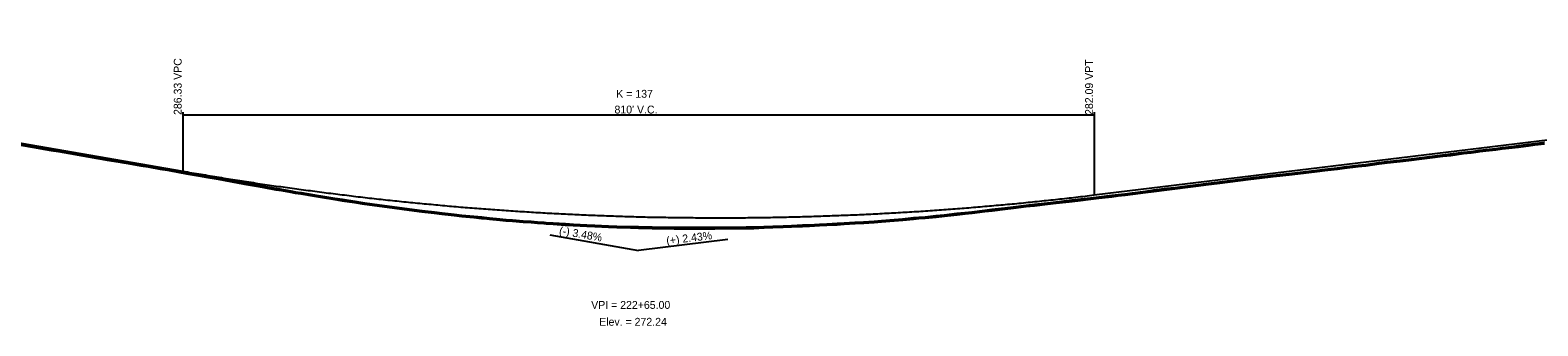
# Model space of a CAD drawing. Extents: x 1876258 to 1926563, y 729739 to 834437.
# Drawn here: x 1900087 to 1901427, y 831298 to 831561 of the extents above; entities that cross this region are included whole.
import ezdxf

# ---------------------------------------------------------------- set-up
doc = ezdxf.new("R2010")
doc.units = 0
for name, color, linetype in [('RD_EX_BldgApp', 7, 'Continuous'), ('RD_EX_H2O_BlueLn', 7, 'Continuous'), ('RD_EX_RailRoad', 7, 'Continuous'), ('RD_HC_Data', 7, 'Continuous'), ('RD_HC_Data_Tic', 7, 'Continuous'), ('RD_HC_TX_Sta50', 7, 'Continuous'), ('RD_PD_ALT5_CL', 7, 'Continuous')]:
    doc.layers.add(name, color=color, linetype=linetype)

msp = doc.modelspace()

# ---------------------------------------------------------------- linework, layer by layer
at = {"layer": 'RD_EX_BldgApp'}
for points in [[(1900079.3, 831459), (1900089.5, 831457.2), (1900095.9, 831456.1), (1900106.1, 831454.4), (1900112.5, 831453.3), (1900122.7, 831451.5), (1900129.1, 831450.4), (1900139.3, 831448.7), (1900145.7, 831447.6), (1900151.1, 831446.6), (1900155.9, 831445.8), (1900165.6, 831444.1), (1900168.8, 831443.6), (1900174.7, 831442.6), (1900185.8, 831440.8), (1900192.2, 831439.7), (1900203, 831437.8), (1900209.4, 831436.7), (1900220.1, 831434.8), (1900226.4, 831433.7), (1900237.2, 831431.8), (1900243.7, 831430.6), (1900254.4, 831428.7), (1900260.8, 831427.6), (1900271.6, 831425.7), (1900277.9, 831424.5), (1900288.7, 831422.5), (1900295.1, 831421.4), (1900305.9, 831419.4), (1900310.7, 831418.7), (1900318.8, 831417.2), (1900323, 831416.5), (1900328.1, 831415.7), (1900340.1, 831413.7), (1900347.3, 831412.5), (1900358.1, 831410.8), (1900364.8, 831409.7), (1900375.8, 831408), (1900382.5, 831407), (1900393.4, 831405.4), (1900400.2, 831404.4), (1900411.2, 831402.9), (1900417.9, 831402), (1900428.8, 831400.7), (1900435.7, 831399.8), (1900446.6, 831398.6), (1900453.4, 831397.7), (1900464.2, 831396.4), (1900471.1, 831395.6)], [(1901312.7, 831445.5), (1901324.4, 831446.9), (1901331.4, 831447.8), (1901342.9, 831449.2), (1901350, 831450), (1901361.4, 831451.5), (1901368.2, 831452.3), (1901374.3, 831453.1), (1901375.8, 831453.3), (1901381.3, 831454), (1901390.1, 831455), (1901395.8, 831455.7), (1901404.6, 831456.8), (1901410.3, 831457.4), (1901419, 831458.5), (1901424.8, 831459.3), (1901433.4, 831460.3)], [(1900471.1, 831395.6), (1900481.8, 831394.6), (1900488.7, 831393.9), (1900493.2, 831393.5), (1900495.7, 831393.2), (1900504.8, 831392.4), (1900510.3, 831391.8), (1900516, 831391.4), (1900525.5, 831390.6), (1900532.6, 831390.2), (1900538.4, 831389.7), (1900544.1, 831389.3), (1900546.1, 831389.1), (1900552.4, 831388.7), (1900563, 831388), (1900570.2, 831387.6), (1900582.1, 831387), (1900589.3, 831386.7), (1900601.4, 831386.1), (1900608.9, 831385.8), (1900621, 831385.5), (1900628.2, 831385.3), (1900640.4, 831385.1), (1900648, 831385), (1900659.8, 831384.8), (1900671.7, 831384.7), (1900679.1, 831384.7), (1900688.4, 831384.8), (1900695.9, 831384.8), (1900705.4, 831384.9), (1900711.8, 831385), (1900714.6, 831384.9), (1900723.9, 831385), (1900730.7, 831385.1), (1900739.7, 831385.4), (1900747.5, 831385.7), (1900756.7, 831386.1), (1900764.2, 831386.4), (1900774, 831386.8), (1900780, 831387.1), (1900789.1, 831387.5), (1900795.5, 831387.8), (1900804.7, 831388.3), (1900811, 831388.7), (1900820.6, 831389.3), (1900828.3, 831389.8), (1900837.7, 831390.4), (1900844.2, 831390.9), (1900855.4, 831391.7), (1900863, 831392.4), (1900872.6, 831393.3), (1900877.3, 831393.7), (1900883, 831394.1), (1900892.6, 831395.1), (1900900, 831395.9), (1900911.3, 831397.2), (1900918.5, 831398), (1900924.6, 831398.7), (1900936, 831400), (1900942.4, 831400.7), (1900953.9, 831402.1), (1900961.3, 831403), (1900972.7, 831404.4), (1900980.1, 831405.2), (1900991.7, 831406.6), (1900999.3, 831407.5), (1901011, 831408.8), (1901018.5, 831409.7), (1901030.2, 831411), (1901037.4, 831411.8), (1901048.9, 831413.2), (1901054.5, 831413.9), (1901060.6, 831414.7), (1901067.5, 831415.6), (1901078.8, 831417), (1901086.1, 831417.9), (1901097.8, 831419.4), (1901104.9, 831420.3), (1901116.3, 831421.7), (1901123.4, 831422.6), (1901134.8, 831424.1), (1901142.3, 831425), (1901153.9, 831426.5), (1901160.9, 831427.4), (1901172.4, 831428.7), (1901180, 831429.6), (1901192.1, 831431.1), (1901198.1, 831431.8), (1901209, 831433), (1901214, 831433.5), (1901221.4, 831434.4), (1901231.4, 831435.6), (1901238.2, 831436.5), (1901249.4, 831437.8), (1901255.5, 831438.6), (1901267.8, 831440), (1901274.5, 831440.8), (1901286.3, 831442.3), (1901293.4, 831443.2), (1901305.1, 831444.6), (1901312.7, 831445.5)]]:
    msp.add_lwpolyline(points, dxfattribs=at)
at = {"layer": 'RD_EX_H2O_BlueLn'}
for p, q in [((1900223.1, 831488.4), (1900223.1, 831435.9)), ((1900223.1, 831485.9), (1901033.1, 831485.9)), ((1901033.1, 831488.4), (1901033.1, 831414.8))]:
    msp.add_line(p, q, dxfattribs=at)
at = {"layer": 'RD_HC_Data_Tic'}
msp.add_lwpolyline([(1900079.5, 831460.2), (1900089.7, 831458.4), (1900096.1, 831457.3), (1900106.3, 831455.6), (1900112.7, 831454.5), (1900122.9, 831452.7), (1900129.3, 831451.6), (1900139.5, 831449.9), (1900145.9, 831448.8), (1900151.3, 831447.8), (1900156.1, 831447), (1900165.8, 831445.3), (1900169, 831444.8), (1900174.9, 831443.8), (1900186, 831442), (1900192.4, 831440.9), (1900203.2, 831439), (1900209.6, 831438), (1900220.3, 831436.1), (1900226.7, 831434.9), (1900237.4, 831433), (1900243.9, 831431.8), (1900254.6, 831429.9), (1900261, 831428.8), (1900271.8, 831426.9), (1900278.2, 831425.7), (1900288.9, 831423.8), (1900295.3, 831422.6), (1900306.1, 831420.7), (1900310.9, 831419.9), (1900319, 831418.5), (1900323.2, 831417.7), (1900328.3, 831416.9), (1900340.3, 831414.9), (1900347.5, 831413.7), (1900358.3, 831412), (1900365, 831411), (1900376, 831409.3), (1900382.7, 831408.2), (1900393.6, 831406.6), (1900400.4, 831405.6), (1900411.4, 831404.1), (1900418.1, 831403.2), (1900428.9, 831401.9), (1900435.8, 831401.1), (1900446.7, 831399.8), (1900453.5, 831399), (1900464.4, 831397.7), (1900471.2, 831396.9), (1900481.9, 831395.8), (1900488.9, 831395.2), (1900493.3, 831394.7), (1900495.8, 831394.5), (1900504.9, 831393.6), (1900510.4, 831393.1), (1900516.1, 831392.6), (1900525.6, 831391.8), (1900532.7, 831391.4), (1900538.5, 831391), (1900544.2, 831390.5), (1900546.2, 831390.4), (1900552.4, 831389.9), (1900563.1, 831389.3), (1900570.3, 831388.9), (1900582.2, 831388.2), (1900589.3, 831387.9), (1900601.5, 831387.3), (1900609, 831387.1), (1900621, 831386.8), (1900628.2, 831386.6), (1900640.4, 831386.3), (1900648, 831386.2), (1900659.8, 831386), (1900671.7, 831386), (1900679.1, 831386), (1900688.4, 831386), (1900695.9, 831386), (1900705.4, 831386.2), (1900711.8, 831386.2), (1900714.6, 831386.2), (1900723.9, 831386.3), (1900730.7, 831386.4), (1900739.6, 831386.7), (1900747.4, 831387), (1900756.7, 831387.3), (1900764.1, 831387.6), (1900774, 831388.1), (1900780, 831388.3), (1900789, 831388.8), (1900795.4, 831389.1), (1900804.6, 831389.6), (1900811, 831389.9), (1900820.5, 831390.5), (1900828.2, 831391), (1900837.6, 831391.6), (1900844.1, 831392.2), (1900855.3, 831393), (1900862.9, 831393.6), (1900872.4, 831394.6), (1900877.2, 831395), (1900882.9, 831395.4), (1900892.5, 831396.4), (1900899.9, 831397.2), (1900911.2, 831398.5), (1900918.3, 831399.2), (1900924.5, 831399.9), (1900935.9, 831401.3), (1900942.2, 831402), (1900953.8, 831403.4), (1900961.1, 831404.2), (1900972.6, 831405.6), (1900980, 831406.5), (1900991.5, 831407.8), (1900999.2, 831408.8), (1901010.8, 831410.1), (1901018.4, 831410.9), (1901030, 831412.2), (1901037.3, 831413.1), (1901048.7, 831414.5), (1901054.4, 831415.2), (1901060.4, 831415.9), (1901067.3, 831416.8), (1901078.6, 831418.2), (1901086, 831419.2), (1901097.7, 831420.7), (1901104.7, 831421.5), (1901116.1, 831422.9), (1901123.2, 831423.8), (1901134.6, 831425.3), (1901142.1, 831426.2), (1901153.8, 831427.7), (1901160.8, 831428.6), (1901172.2, 831430), (1901179.8, 831430.8), (1901192, 831432.3), (1901197.9, 831433), (1901208.8, 831434.2), (1901213.8, 831434.8), (1901221.2, 831435.6), (1901231.2, 831436.9), (1901238, 831437.7), (1901249.2, 831439), (1901255.3, 831439.8), (1901267.7, 831441.3), (1901274.3, 831442), (1901286.1, 831443.5), (1901293.2, 831444.4), (1901304.9, 831445.8), (1901312.6, 831446.7), (1901324.2, 831448.1), (1901331.3, 831449), (1901342.8, 831450.4), (1901349.9, 831451.3), (1901361.3, 831452.7), (1901368.1, 831453.5), (1901374.1, 831454.3), (1901375.6, 831454.5), (1901381.1, 831455.2), (1901390, 831456.2), (1901395.7, 831457), (1901404.4, 831458), (1901410.1, 831458.7), (1901418.8, 831459.8), (1901424.6, 831460.5), (1901433.3, 831461.6)], dxfattribs=at)
at = {"layer": 'RD_HC_TX_Sta50'}
for p in [(1900549.3, 831379.2), (1900707.5, 831375.2)]:
    msp.add_line(p, (1900628.1, 831365.5), dxfattribs=at)
at = {"layer": 'RD_PD_ALT5_CL'}
for p, q in [((1901033.1, 831414.8), (1902238.1, 831561.3)), ((1900053.1, 831465.5), (1900223.1, 831435.9))]:
    msp.add_line(p, q, dxfattribs=at)
msp.add_spline([(1900223.1, 831435.9), (1900239.3, 831433.2), (1900255.5, 831430.5), (1900271.7, 831427.9), (1900287.9, 831425.4), (1900304.1, 831423), (1900320.3, 831420.8), (1900336.5, 831418.6), (1900352.7, 831416.5), (1900368.9, 831414.5), (1900385.1, 831412.5), (1900401.3, 831410.7), (1900417.5, 831409), (1900433.7, 831407.4), (1900449.9, 831405.9), (1900466.1, 831404.4), (1900482.3, 831403.1), (1900498.5, 831401.9), (1900514.7, 831400.7), (1900530.9, 831399.7), (1900547.1, 831398.7), (1900563.3, 831397.9), (1900579.5, 831397.1), (1900595.7, 831396.5), (1900611.9, 831395.9), (1900628.1, 831395.4), (1900644.3, 831395), (1900660.5, 831394.8), (1900676.7, 831394.6), (1900692.9, 831394.5), (1900709.1, 831394.5), (1900725.3, 831394.6), (1900741.5, 831394.8), (1900757.7, 831395.1), (1900773.9, 831395.5), (1900790.1, 831396), (1900806.3, 831396.6), (1900822.5, 831397.2), (1900838.7, 831398), (1900854.9, 831398.9), (1900871.1, 831399.8), (1900887.3, 831400.9), (1900903.5, 831402.1), (1900919.7, 831403.3), (1900935.9, 831404.7), (1900952.1, 831406.1), (1900968.3, 831407.6), (1900984.5, 831409.3), (1901000.7, 831411), (1901016.9, 831412.8), (1901033.1, 831414.8)], degree=3, dxfattribs=at)

# ---------------------------------------------------------------- texts
at = {"layer": 'RD_EX_H2O_BlueLn'}
for s, p in [('K = 137', (1900608.4, 831501.2)), ("810' V.C.", (1900606.8, 831487.2))]:
    msp.add_text(s, height=7, dxfattribs=at).set_placement(p)
at = {"layer": 'RD_EX_RailRoad'}
for s, p in [('286.33 VPC', (1900222.1, 831485.9)), ('282.09 VPT', (1901032.1, 831485.9))]:
    msp.add_text(s, height=7, rotation=90, dxfattribs=at).set_placement(p)
at = {"layer": 'RD_HC_Data'}
for s, p in [('VPI = 222+65.00', (1900586.1, 831313.5)), ('Elev. = 272.24', (1900593.2, 831298.5))]:
    msp.add_text(s, height=7, dxfattribs=at).set_placement(p)
at = {"layer": 'RD_HC_TX_Sta50'}
for s, rotation, p in [('(-) 3.48%', 350.1334, (1900557.2, 831379.9)), ('(+) 2.43%', 6.9344, (1900653.3, 831370.6))]:
    msp.add_text(s, height=7, rotation=rotation, dxfattribs=at).set_placement(p)

doc.saveas('drawing.dxf')
